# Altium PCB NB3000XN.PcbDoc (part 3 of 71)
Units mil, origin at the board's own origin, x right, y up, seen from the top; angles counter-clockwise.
Board outline 9527.56 x 6929.77 mil, 6 copper layers (Top Layer, GND+SHIELD, MidLayer1, MidLayer2, P2 - 3V3+5V0, Bottom Layer), stack 62.375 mil thick; 832 components, 1027 nets, 4655 pads, 4981 vias.
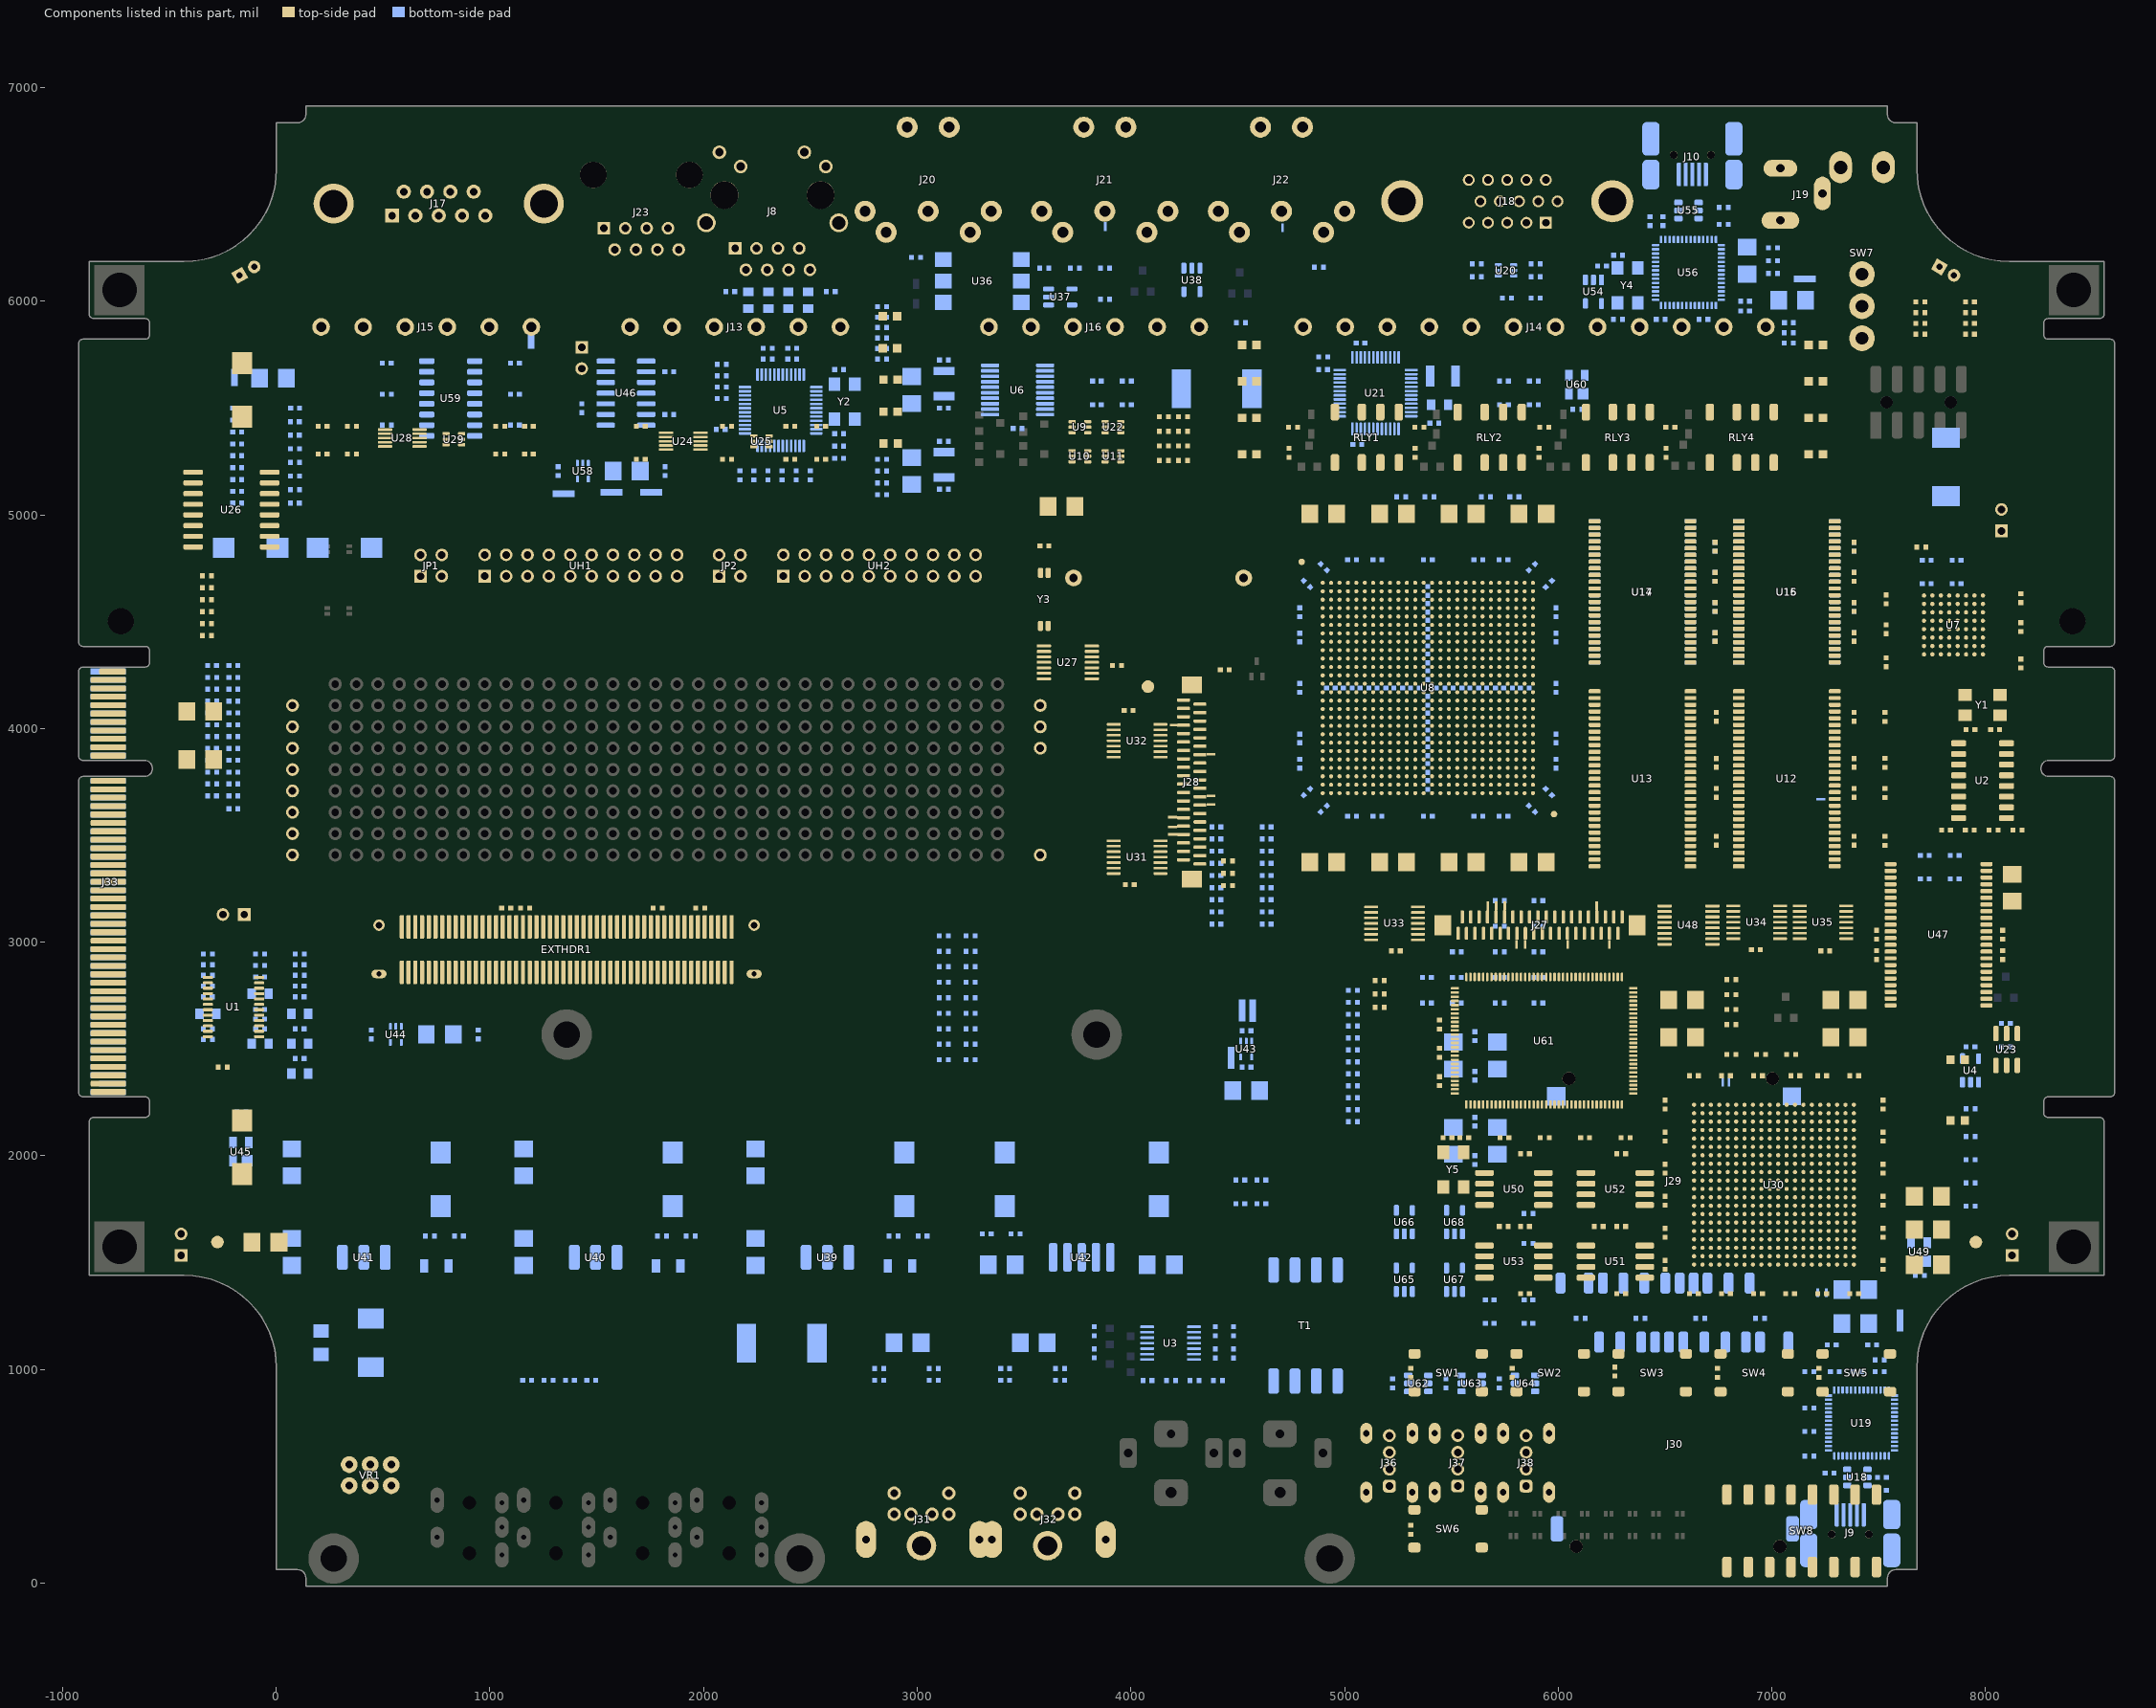
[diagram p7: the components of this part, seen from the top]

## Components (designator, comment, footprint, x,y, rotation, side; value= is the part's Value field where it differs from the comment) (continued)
R228 "100R 1%" RESC1005-STAR 3125,2812.5 r180 bottom locked (schematic designator R13)
R229 "100R 1%" RESC1005-STAR 3125,2667.5 r180 bottom locked (schematic designator R14)
R230 "100R 1%" RESC1005-STAR 3125,2522.5 r180 bottom locked (schematic designator R15)
R231 "100R 1%" RESC1005-STAR 3125,2595 r180 bottom locked (schematic designator R16)
R232 "4K7 1%" RESC1005-STAR 3250,2450 r0 bottom locked (schematic designator R17)
R233 "100R 1%" RESC1005-STAR 3125,2450 r180 bottom locked (schematic designator R18)
R234 "2K2 1%" RESC1005-STAR 1165,3160 r180 top (schematic designator R1)
R235 "2K2 1%" RESC1005-STAR 7530,3474.85 r270 top locked (schematic designator R275)
R236 "4K7 1%" RESC1005-STAR 5040,2719.09 r180 bottom locked (schematic designator R8)
R237 "4K7 1%" RESC1005-STAR 5040,2663.18 r180 bottom locked (schematic designator R7)
R238 "4K7 1%" RESC1005-STAR 5040,2607.27 r180 bottom locked (schematic designator R6)
R239 "4K7 1%" RESC1005-STAR 5040,2551.36 r180 bottom locked (schematic designator R5)
R240 "4K7 1%" RESC1005-STAR 5040,2495.45 r180 bottom locked (schematic designator R4)
R241 "4K7 1%" RESC1005-STAR 5040,2439.55 r180 bottom locked (schematic designator R3)
R242 "4K7 1%" RESC1005-STAR 5040,2383.64 r180 bottom locked (schematic designator R2)
R243 "4K7 1%" RESC1005-STAR 5040,2327.73 r180 bottom locked (schematic designator R1)
R244 "27R 1%" RESC1005-STAR 6280,5915 r180 bottom locked (schematic designator R1)
R245 "2K7 1%" RESC1005-STAR 7080,5805 r180 bottom locked (schematic designator R2)
R246 "5K6 1%" RESC1005-STAR 7080,5852.5 r180 bottom locked (schematic designator R3)
R247 "10K 1%" RESC1005-STAR 6775,6440 r180 bottom locked (schematic designator R4)
R248 "4K7 1%" RESC1005-STAR 7692.5,1440 r180 bottom locked (schematic designator R1000)
R249 "27R 1%" RESC1005-STAR 6775,6360 r180 bottom locked (schematic designator R6)
R250 "4K7 1%" RESC1005-STAR 7005,6250 r180 bottom locked (schematic designator R9)
R251 "4K7 1%" RESC1005-STAR 7005,6130 r180 bottom locked (schematic designator R8)
R252 "4K7 1%" RESC1005-STAR 7005,6190 r0 bottom locked (schematic designator R7)
R253 "4K7 1%" RESC1005-STAR 6665,1240 r180 bottom locked (schematic designator R1)
R254 "4K7 1%" RESC1005-STAR 6105,1240 r180 bottom locked (schematic designator R2)
R255 "4K7 1%" RESC1005-STAR 6385,1240 r0 bottom locked (schematic designator R1)
R256 "4K7 1%" RESC1005-STAR 6945,1240 r0 bottom locked (schematic designator R2)
R257 "12K 1%" RESC1005-STAR 5937.51,2085 r0 top locked (schematic designator R1)
R258 "12K 1%" RESC1005-STAR 6126.25,2085 r0 top locked (schematic designator R2)
R259 "12K 1%" RESC1005-STAR 6315,2085 r0 top locked (schematic designator R3)
R260 "10K 1%" RESC1005-STAR 5040,2775 r180 bottom locked (schematic designator R4)
R261 "150R 1%" RESC1005-STAR 5040,2271.82 r180 bottom locked (schematic designator R5)
R262 "150R 1%" RESC1005-STAR 5040,2215.91 r180 bottom locked (schematic designator R6)
R263 "150R 1%" RESC1005-STAR 5040,2160 r180 bottom locked (schematic designator R7)
R264 "2K2 1%" RESC1005-STAR 6810,2475 r0 top locked (schematic designator R269)
R265 "2K2 1%" RESC1005-STAR 6950,2475 r0 top locked (schematic designator R270)
R266 "2K2 1%" RESC1005-STAR 7090,2475 r0 top locked (schematic designator R271)
R267 "100R 1%" RESC1005-STAR 7926.99,5997 r0 top (schematic designator R154)
R268 "100R 1%" RESC1005-STAR 7695,5997 r0 top (schematic designator R155)
R269 "100R 1%" RESC1005-STAR 7926.99,5846 r0 top (schematic designator R156)
R270 "100R 1%" RESC1005-STAR 7695,5846 r0 top (schematic designator R157)
R271 "4K7 1%" RESC1005-STAR 6090,5495 r180 bottom locked (schematic designator R1000)
R272 "10K 1%" RESC1005-STAR 5445,2482.51 r90 top locked (schematic designator R268)
R273 "10K 1%" RESC1005-STAR 5445,2615 r90 top locked (schematic designator R264)
R274 "10K 1%" RESC1005-STAR 5225,935 r270 bottom locked (schematic designator R265)
R275 "10K 1%" RESC1005-STAR 5475,935 r90 bottom locked (schematic designator R266)
R276 "10K 1%" RESC1005-STAR 5725,935 r270 bottom locked (schematic designator R267)
R277 "4K7 1%" RESC1005-STAR 1785.16,3160.02 r180 top
R278 "4K7 1%" RESC1005-STAR 1985.52,3160.03 r180 top
R279 "4K7 1%" RESC1005-STAR 7926.99,5946.67 r0 top
R280 "4K7 1%" RESC1005-STAR 7695,5946.67 r0 top
R281 "4K7 1%" RESC1005-STAR 7926.99,5896.33 r0 top
R282 "4K7 1%" RESC1005-STAR 7695,5896.33 r0 top
R283 "4K7 1%" RESC1005-STAR 1076.56,3160 r180 top
RLY1 "IMO3 - 5VDC" IM03GR 4955,5245 r270 top locked
RLY2 "IMO3 - 5VDC" IM03GR 5530,5245 r270 top locked (schematic designator RLY1)
RLY3 "IMO3 - 5VDC" IM03GR 6130,5245 r270 top locked (schematic designator RLY1)
RLY4 "IMO3 - 5VDC" IM03GR 6710,5245 r270 top locked (schematic designator RLY1)
SW1 "SPNO" SW_DTSM-61NT/R 5485,985.39 r0 top locked
SW2 "SPNO" SW_DTSM-61NT/R 5962.5,985.39 r0 top locked
SW3 "SPNO" SW_DTSM-61NT/R 6440,985.39 r0 top locked
SW4 "SPNO" SW_DTSM-61NT/R 6917.5,985 r0 top locked
SW5 "SPNO" SW_DTSM-61NT/R 7395,985 r0 top locked
SW6 "SPNO" SW_DTSM-61NT/R 5485,255 r180 top locked (schematic designator SW1)
SW7 "SPDT SUB" T8019L-TNQ 7422,6920 r0 bottom locked (schematic designator SW1)
SW8 "219-8LPST" 219-8LPST 7140,245 r90 top locked (schematic designator SW1)
T1 "PT4812" PT4812 4668,1466 r0 bottom locked
TP1 "GND" TESTPIN 76.12,4108.23 r180 top locked
TP2 "5V0" TESTPIN 76.12,4008.23 r180 top locked
TP3 "+B" TESTPIN 3576.12,3908.23 r0 top locked
TP4 "3V3" TESTPIN 76.12,3908.23 r180 top locked
TP5 "2V5" TESTPIN 76.12,3808.23 r180 top locked
TP6 "1V8" TESTPIN 76.12,3708.23 r180 top locked
TP7 "1V2" TESTPIN 76.12,3608.23 r180 top locked
TP8 "GND" TESTPIN 3576.12,4008.23 r0 top locked
TP9 "MIXER LEFT" TESTPIN 76.12,3508.23 r180 top locked (schematic designator TP1)
TP10 "MIXER RIGHT" TESTPIN 76.12,3408.23 r180 top locked (schematic designator TP2)
TP11 "32K768HZ" TESTPIN 3576.12,4108.23 r0 top locked (schematic designator TP1)
TP12 "VBATT" TESTPIN 3576.12,3408.23 r0 top locked (schematic designator TP15)
U1 "CS4270" TSSOP-24 -320,2835 r270 top locked
U2 "ICS307-02" SOIC127P600-16 7986.38,3756.34 r270 top locked (schematic designator U1)
U3 "74HCU04" TSSOP14 4295,1200 r180 bottom locked (schematic designator U1)
U4 "SN74LVC1G04DBV" SOT95P280-5 7930,2400 r180 bottom locked (schematic designator U1)
U5 "RTL8201CL" TSQFP50P900X900-48 2360.87,5490 r90 bottom locked (schematic designator U1)
U6 "SN74LVC244ADB" SOP65P780-20 3470,5585 r270 bottom locked (schematic designator U2)
U7 "S29GL128P11FFI010" BGA100P8X8-64 7850,4485 r180 top locked (schematic designator U1)
U8 "XC3S1400AN-4FG676C" BGA100P26X26-676 5390,4190 r0 top locked (schematic designator U1)
U9 "SMF05C" SC70_6L 3725,5436.18 r270 top locked (schematic designator U2)
U10 "SMF05C" SC70_6L 3725,5300 r270 top locked (schematic designator U2)
U11 "SMF05C" SC70_6L 3880,5300 r270 top locked (schematic designator U2)
U12 "SDRAM-16Mx16" TSOP80P1176-54 7070,3765 r270 top locked (schematic designator U1)
U13 "SDRAM-16Mx16" TSOP80P1176-54 6395,3765 r270 top locked (schematic designator U2)
U14 "SRAM-256Kx16" TSOP80P1176-44 6395,4640 r270 bottom locked (schematic designator U1_SM)
U15 "SRAM-256Kx16" TSOP80P1176-44 7070,4640 r270 bottom locked (schematic designator U1_SM)
U16 "SRAM-256Kx16" TSOP80P1176-44 7070,4640 r270 top locked (schematic designator U1)
U17 "SRAM-256Kx16" TSOP80P1176-44 6395,4640 r270 top locked (schematic designator U2)
U18 "NUP2201MR6T1G" TSOP95P275-6 7400,495 r90 bottom locked (schematic designator U2)
U19 "CY7C68001-56LFC" QFN50P800X800_HS-57 7420,750 r180 bottom locked (schematic designator U3)
U20 "SMF05C" SC70_6L 5792.17,6170 r270 bottom locked (schematic designator U1)
U21 "THS8134BCPHP" TSQFP50P900X900_HS-48 5145,5570 r180 bottom locked (schematic designator U1)
U22 "SMF05C" SC70_6L 3880,5436.18 r270 top locked (schematic designator U2)
U23 "DS2502P" DSO-C6-D4 8099,2498.01 r180 top locked (schematic designator U1)
U24 "ADC084S021" TSSOP50P490-10AN 1905,5345 r180 top locked (schematic designator U1)
U25 "SMF05C" SC70_6L 2235,5370 r270 top locked (schematic designator U2)
U26 "PT2300-S" SOIC127P1030-16N -210,5025 r0 top locked (schematic designator U1)
U27 "PCF2123TS" TSOP65P640-14AN 3705,4310 r0 top locked (schematic designator U5)
U28 "DAC084S085CIMM" TSSOP50P490-10AN 590,5360 r0 top locked (schematic designator U1)
U29 "SMF05C" SC70_6L 795,5380 r270 top locked (schematic designator U2)
U30 "XC3S400AN-4FGG400C" FGG400 7010,1865 r270 top locked (schematic designator U1)
U31 "74VHC04" TSSOP14 3920,3475 r0 top locked (schematic designator U1)
U32 "74VHC04" TSSOP14 3920,4020 r0 top locked (schematic designator U1)
U33 "74VHC04" TSSOP14 5125,3165 r0 top locked (schematic designator U1)
U34 "74VHC04" TSSOP14 6820,3170 r0 top locked (schematic designator U1)
U35 "74VHC04" TSSOP14 7130,3170 r0 top locked (schematic designator U1)
U36 "4N35S" H11L1SR2VM 3305,6095 r90 bottom locked (schematic designator U1)
U37 "SN74LVC1G04DBV" SOT95P280-5 3670,6020 r90 bottom locked (schematic designator U2)
U38 "SN74LVC1G04DBV" SOT95P280-5 4285.84,6100 r0 bottom locked (schematic designator U3)
U39 "AP1084KL" TO254P-3N 2580,1775 r90 bottom locked (schematic designator U1)
U40 "AP1084KL" TO254P-3N 1495,1775 r90 bottom locked (schematic designator U1)
U41 "AP1084KL" TO254P-3N 410,1775 r90 bottom locked (schematic designator U1)
U42 "NCP630A" TO-263-2 3770,1525 r180 bottom locked (schematic designator U1)
U43 "TC1017R-3.3VLTTR" SOT65P210X80-5N 4540,2500 r270 bottom locked (schematic designator U1)
U44 "TC1017R-3.3VLTTR" SOT65P210X80-5N 560,2568.37 r270 bottom locked (schematic designator U1)
U45 "MAX6315US26D1" SOT143 -165.45,2020 r180 bottom locked (schematic designator U2000)
U46 "ISL8491IB" SOIC127P600-14N 1637.05,5570.08 r180 bottom locked (schematic designator U1)
U47 "SRAM-256Kx16" TSOP80P1176-44 7780,3035 r270 top locked (schematic designator U1_SM)
U48 "XPT2046" TSOP65P640-16AN 6610,3080 r0 top locked (schematic designator U1)
U49 "MAX6315US26D1" SOT143 7689.55,1550 r180 bottom locked (schematic designator U1000)
U50 "M25P80-VMW6 8Mbit Serial Flash" SOIC8-200-BODY 5655,1920 r270 top locked (schematic designator U1)
U51 "M25P80-VMW6 8Mbit Serial Flash" SOIC8-200-BODY 6130,1580 r270 top locked (schematic designator U1)
U52 "M25P80-VMW6 8Mbit Serial Flash" SOIC8-200-BODY 6130,1920 r270 top locked (schematic designator U1)
U53 "M25P80-VMW6 8Mbit Serial Flash" SOIC8-200-BODY 5655,1580 r270 top locked (schematic designator U2)
U54 "SN74LVC1G04DBV" SOT95P280-5 6165,6045 r0 bottom locked (schematic designator U1)
U55 "NUP2201MR6T1G" TSOP95P275-6 6610,6425 r270 bottom locked (schematic designator U2)
U56 "CY7C68001-56LFC" QFN50P800X800_HS-57 6610,6135 r0 bottom locked (schematic designator U3)
U58 "TC1017R-3.3VLTTR" SOT65P210X80-5N 1435,5205 r270 bottom locked (schematic designator U1)
U59 "HIN232ACBNZ-T" SOIC127P600-16 816.8,5545.08 r270 bottom locked (schematic designator U45)
U60 "MAX6315US26D1" SOT143 6087.05,5610 r180 bottom locked (schematic designator U1000)
U61 "ISP1760" SOT425-1 5570,2240 r0 top locked (schematic designator U59)
U62 "NUP2201MR6T1G" TSOP95P275-6 5345,935 r270 bottom locked (schematic designator U60)
U63 "NUP2201MR6T1G" TSOP95P275-6 5595,935 r270 bottom locked (schematic designator U61)
U64 "NUP2201MR6T1G" TSOP95P275-6 5845,935 r270 bottom locked (schematic designator U62)
U65 "SN74LVC1G04DBV" SOT95P280-5 5280,1420 r180 bottom locked
U66 "SN74LVC1G04DBV" SOT95P280-5 5280,1690 r180 bottom locked
U67 "SN74LVC1G04DBV" SOT95P280-5 5515,1420 r180 bottom locked (schematic designator U65)
U68 "SN74LVC1G04DBV" SOT95P280-5 5515,1690 r180 bottom locked (schematic designator U66)
UH1 "2x10 HEADER" HDR2X10 976.12,4713.23 r0 top locked
UH2 "2x10 HEADER" HDR2X10 2373.76,4713.23 r0 top locked
VR1 "2x5K linear" POT-R0911G-A1 440,555 r180 bottom locked
Y1 "20MHZ" XTAL-200X126-4 7986.38,4110 r0 top locked
Y2 "25MHz" XTAL-200X126-4 2660,5530 r270 bottom locked (schematic designator Y1)
Y3 "32.768 kHz 7pF" ECS-71 3595,4605 r90 top locked (schematic designator Y1)
Y4 "24MHz" XTAL-200X126-4 6325,6075 r270 bottom locked (schematic designator Y1)
Y5 "12MHz XTAL" XTAL-200X126-4 5510,1935 r270 top locked (schematic designator Y1)

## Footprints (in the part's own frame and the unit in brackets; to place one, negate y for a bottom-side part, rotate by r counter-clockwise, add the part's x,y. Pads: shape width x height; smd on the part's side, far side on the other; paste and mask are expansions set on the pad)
219-8LPST [mm] "Surface Mount DIP Switch, 8-way, Gull Wing Leads"
  rrect50% 2.44x1.13 smd: 1(-4.3,8.89) 2(-4.3,6.35) 3(-4.3,3.81) 4(-4.3,1.27) 5(-4.3,-1.27) 6(-4.3,-3.81) 7(-4.3,-6.35) 8(-4.3,-8.89) 9(4.3,-8.89) 10(4.3,-6.35) 11(4.3,-3.81) 12(4.3,-1.27) 13(4.3,1.27) 14(4.3,3.81) 15(4.3,6.35) 16(4.3,8.89)
  silkscreen extent -4.42,-11.04 2.68,11.04, body extent -5.1,-11.4 5.08,11.4, height 3.37
0603LED_GREEN [mm]
  rect 1x1 smd paste+0 mask+0: 1(0.85,0) 2(-0.85,0)
  silkscreen extent -1.97,-0.85 1.6,0.85, body extent -0.92,-0.53 1.09,0.53, height 0.46
0603LED_ORANGE [mm]
  rect 1x1 smd paste+0 mask+0: 1(0.85,0) 2(-0.85,0)
  silkscreen extent -1.97,-0.85 1.6,0.85, body extent -0.92,-0.53 1.09,0.53, height 0.46
0603LED_RED [mm]
  rect 1x1 smd paste+0 mask+0: 1(0.85,0) 2(-0.85,0)
  silkscreen extent -1.97,-0.85 1.6,0.85, body extent -0.92,-0.53 1.09,0.53, height 0.46
0603LED_YELLOW [mm]
  rect 1x1 smd paste+0 mask+0: 1(0.85,0) 2(-0.85,0)
  silkscreen extent -1.97,-0.85 1.6,0.85, body extent -0.92,-0.53 1.09,0.53, height 0.46
53751 [mm]
  rrect50% 0.508x2.8 smd: 1(-19.6,-2.7) 2(-19.6,2.7) 3(-18.8,-2.7) 4(-18.8,2.7) 5(-18,-2.7) 6(-18,2.7) 7(-17.2,-2.7) 8(-17.2,2.7) 9(-16.4,-2.7) 10(-16.4,2.7) 11(-15.6,-2.7) 12(-15.6,2.7) 13(-14.8,-2.7) 14(-14.8,2.7) 15(-14,-2.7) 16(-14,2.7) 17(-13.2,-2.7) 18(-13.2,2.7) 19(-12.4,-2.7) 20(-12.4,2.7) 21(-11.6,-2.7) 22(-11.6,2.7) 23(-10.8,-2.7) 24(-10.8,2.7) 25(-10,-2.7) 26(-10,2.7) 27(-9.2,-2.7) 28(-9.2,2.7) 29(-8.4,-2.7) 30(-8.4,2.7) 31(-7.6,-2.7) 32(-7.6,2.7) 33(-6.8,-2.7) 34(-6.8,2.7) 35(-6,-2.7) 36(-6,2.7) 37(-5.2,-2.7) 38(-5.2,2.7) 39(-4.4,-2.7) 40(-4.4,2.7) 41(-3.6,-2.7) 42(-3.6,2.7) 43(-2.8,-2.7) 44(-2.8,2.7) 45(-2,-2.7) 46(-2,2.7) 47(-1.2,-2.7) 48(-1.2,2.7) 49(-0.4,-2.7) 50(-0.4,2.7) 51(0.4,-2.7) 52(0.4,2.7) 53(1.2,-2.7) 54(1.2,2.7) 55(2,-2.7) 56(2,2.7) 57(2.8,-2.7) 58(2.8,2.7) 59(3.6,-2.7) 60(3.6,2.7) 61(4.4,-2.7) 62(4.4,2.7) 63(5.2,-2.7) 64(5.2,2.7) 65(6,-2.7) 66(6,2.7) 67(6.8,-2.7) 68(6.8,2.7) 69(7.6,-2.7) 70(7.6,2.7) 71(8.4,-2.7) 72(8.4,2.7) 73(9.2,-2.7) 74(9.2,2.7) 75(10,-2.7) 76(10,2.7) 77(10.8,-2.7) 78(10.8,2.7) 79(11.6,-2.7) 80(11.6,2.7) 81(12.4,-2.7) 82(12.4,2.7) 83(13.2,-2.7) 84(13.2,2.7) 85(14,-2.7) 86(14,2.7) 87(14.8,-2.7) 88(14.8,2.7) 89(15.6,-2.7) 90(15.6,2.7) 91(16.4,-2.7) 92(16.4,2.7) 93(17.2,-2.7) 94(17.2,2.7) 95(18,-2.7) 96(18,2.7) 97(18.8,-2.7) 98(18.8,2.7) 99(19.6,-2.7) 100(19.6,2.7)
  round 1.35 hole 0.8: MH1(-22.283,-2.9) MH3(22.317,-2.9)
  oval 1.8x1 hole 0.6 slot 1.4 at 0 deg: MH2(-22.283,2.9) MH4(22.317,2.9)
  silkscreen extent -30,-4.77 30.05,4.5, body extent -30.33,-4.4 30.37,4.4, height 11.7
482040001 [mm] "USB A Type Up-Right Reverse Connector, Pb-Free version"
  rrect50% 1.52x1.52 hole 0.9: 1(0,7.73)
  round 1.52 hole 0.9: 2(0,9.73) 3(0,11.73) 4(0,13.73)
  oval 1.4x2.5 hole 0.75 slot 1.5 at 90 deg: MH1(-2.735,7) MH2(2.735,7) MH3(-2.735,14) MH4(2.735,14)
  silkscreen extent -3.6,-4.64 3.6,15.75, body extent -3.61,-4.71 3.59,14.54, height 14.68
955012881 [mm] "Connector; PCB Jack, Thru-Hole; 1-Port, 8 Positions, 8 Loaded; Shielded without Lightpipes; Vertical"
  rect 1.5x1.5 hole 0.9: 1(-4.445,3.43)
  round 1.5 hole 0.9: 2(-3.175,5.97) 3(-1.905,3.43) 4(-0.635,5.97) 5(0.635,3.43) 6(1.905,5.97) 7(3.175,3.43) 8(4.445,5.97)
  round 3.15 hole 3.15 unplated: MH1(-5.715,-2.92) MH2(5.715,-2.92)
  silkscreen extent -7.62,-10.8 7.62,7.3, body extent -7.53,-145.72 7.51,7.04, height 23.16
BGA100P8X8-64 [mil] "AMD 64-Ball Fortfied Ball grid Array (FBGA)"
  round 20 smd: A1(-137.8,-137.8) A2(-137.8,-98.43) A3(-137.8,-59.06) A4(-137.8,-19.68) A5(-137.8,19.68) A6(-137.8,59.06) A7(-137.8,98.43) A8(-137.8,137.8) B1(-98.43,-137.8) B2(-98.43,-98.43) B3(-98.43,-59.06) B4(-98.43,-19.69) B5(-98.43,19.68) B6(-98.43,59.06) B7(-98.43,98.43) B8(-98.43,137.8) C1(-59.06,-137.8) C2(-59.06,-98.43) C3(-59.06,-59.06) C4(-59.06,-19.69) C5(-59.06,19.68) C6(-59.06,59.06) C7(-59.06,98.43) C8(-59.06,137.8) D1(-19.69,-137.8) D2(-19.69,-98.43) D3(-19.69,-59.06) D4(-19.69,-19.69) D5(-19.69,19.68) D6(-19.69,59.06) D7(-19.69,98.43) D8(-19.69,137.8) E1(19.68,-137.8) E2(19.68,-98.43) E3(19.68,-59.06) E4(19.68,-19.69) E5(19.68,19.68) E6(19.68,59.06) E7(19.68,98.43) E8(19.68,137.8) F1(59.05,-137.8) F2(59.05,-98.43) F3(59.05,-59.06) F4(59.05,-19.69) F5(59.05,19.68) F6(59.05,59.06) F7(59.05,98.43) F8(59.05,137.8) G1(98.42,-137.8) G2(98.42,-98.43) G3(98.42,-59.06) G4(98.42,-19.69) G5(98.42,19.68) G6(98.42,59.06) G7(98.43,98.43) G8(98.42,137.8) H1(137.8,-137.8) H2(137.8,-98.43) H3(137.8,-59.06) H4(137.8,-19.69) H5(137.8,19.68) H6(137.8,59.06) H7(137.8,98.43) H8(137.8,137.8)
  silkscreen extent -256,-250 256,217, body extent -250,-213 252,211, height 39
BGA100P26X26-676 [mm]
  round 0.483 smd: A1(-12.5,12.5) A2(-11.5,12.5) A3(-10.5,12.5) A4(-9.5,12.5) A5(-8.5,12.5) A6(-7.5,12.5) A7(-6.5,12.5) A8(-5.5,12.5) A9(-4.5,12.5) A10(-3.5,12.5) A11(-2.5,12.5) A12(-1.5,12.5) A13(-0.5,12.5) A14(0.5,12.5) A15(1.5,12.5) A16(2.5,12.5) A17(3.5,12.5) A18(4.5,12.5) A19(5.5,12.5) A20(6.5,12.5) A21(7.5,12.5) A22(8.5,12.5) A23(9.5,12.5) A24(10.5,12.5) A25(11.5,12.5) A26(12.5,12.5) AA1(-12.5,-7.5) AA2(-11.5,-7.5) AA3(-10.5,-7.5) AA4(-9.5,-7.5) AA5(-8.5,-7.5) AA6(-7.5,-7.5) AA7(-6.5,-7.5) AA8(-5.5,-7.5) AA9(-4.5,-7.5) AA10(-3.5,-7.5) AA11(-2.5,-7.5) AA12(-1.5,-7.5) AA13(-0.5,-7.5) AA14(0.5,-7.5) AA15(1.5,-7.5) AA16(2.5,-7.5) AA17(3.5,-7.5) AA18(4.5,-7.5) AA19(5.5,-7.5) AA20(6.5,-7.5) AA21(7.5,-7.5) AA22(8.5,-7.5) AA23(9.5,-7.5) AA24(10.5,-7.5) AA25(11.5,-7.5) AA26(12.5,-7.5) AB1(-12.5,-8.5) AB2(-11.5,-8.5) AB3(-10.5,-8.5) AB4(-9.5,-8.5) AB5(-8.5,-8.5) AB6(-7.5,-8.5) AB7(-6.5,-8.5) AB8(-5.5,-8.5) AB9(-4.5,-8.5) AB10(-3.5,-8.5) AB11(-2.5,-8.5) AB12(-1.5,-8.5) AB13(-0.5,-8.5) AB14(0.5,-8.5) AB15(1.5,-8.5) AB16(2.5,-8.5) AB17(3.5,-8.5) AB18(4.5,-8.5) AB19(5.5,-8.5) AB20(6.5,-8.5) AB21(7.5,-8.5) AB22(8.5,-8.5) AB23(9.5,-8.5) AB24(10.5,-8.5) AB25(11.5,-8.5) AB26(12.5,-8.5) AC1(-12.5,-9.5) AC2(-11.5,-9.5) AC3(-10.5,-9.5) AC4(-9.5,-9.5) AC5(-8.5,-9.5) AC6(-7.5,-9.5) AC7(-6.5,-9.5) AC8(-5.5,-9.5) AC9(-4.5,-9.5) AC10(-3.5,-9.5) AC11(-2.5,-9.5) AC12(-1.5,-9.5) AC13(-0.5,-9.5) AC14(0.5,-9.5) AC15(1.5,-9.5) AC16(2.5,-9.5) AC17(3.5,-9.5) AC18(4.5,-9.5) AC19(5.5,-9.5) AC20(6.5,-9.5) AC21(7.5,-9.5) AC22(8.5,-9.5) AC23(9.5,-9.5) AC24(10.5,-9.5) AC25(11.5,-9.5) AC26(12.5,-9.5) AD1(-12.5,-10.5) AD2(-11.5,-10.5) AD3(-10.5,-10.5) AD4(-9.5,-10.5) AD5(-8.5,-10.5) AD6(-7.5,-10.5) AD7(-6.5,-10.5) AD8(-5.5,-10.5) AD9(-4.5,-10.5) AD10(-3.5,-10.5) AD11(-2.5,-10.5) AD12(-1.5,-10.5) AD13(-0.5,-10.5) AD14(0.5,-10.5) AD15(1.5,-10.5) AD16(2.5,-10.5) AD17(3.5,-10.5) AD18(4.5,-10.5) AD19(5.5,-10.5) AD20(6.5,-10.5) AD21(7.5,-10.5) AD22(8.5,-10.5) AD23(9.5,-10.5) AD24(10.5,-10.5) AD25(11.5,-10.5) AD26(12.5,-10.5) AE1(-12.5,-11.5) AE2(-11.5,-11.5) AE3(-10.5,-11.5) AE4(-9.5,-11.5) AE5(-8.5,-11.5) AE6(-7.5,-11.5) AE7(-6.5,-11.5) AE8(-5.5,-11.5) AE9(-4.5,-11.5) AE10(-3.5,-11.5) AE11(-2.5,-11.5) AE12(-1.5,-11.5) AE13(-0.5,-11.5) AE14(0.5,-11.5) AE15(1.5,-11.5) AE16(2.5,-11.5) AE17(3.5,-11.5) AE18(4.5,-11.5) AE19(5.5,-11.5) AE20(6.5,-11.5) AE21(7.5,-11.5) AE22(8.5,-11.5) AE23(9.5,-11.5) AE24(10.5,-11.5) AE25(11.5,-11.5) AE26(12.5,-11.5) AF1(-12.5,-12.5) AF2(-11.5,-12.5) AF3(-10.5,-12.5) AF4(-9.5,-12.5) AF5(-8.5,-12.5) AF6(-7.5,-12.5) AF7(-6.5,-12.5) AF8(-5.5,-12.5) AF9(-4.5,-12.5) AF10(-3.5,-12.5) AF11(-2.5,-12.5) AF12(-1.5,-12.5) AF13(-0.5,-12.5) AF14(0.5,-12.5) AF15(1.5,-12.5) AF16(2.5,-12.5) AF17(3.5,-12.5) AF18(4.5,-12.5) AF19(5.5,-12.5) AF20(6.5,-12.5) AF21(7.5,-12.5) AF22(8.5,-12.5) AF23(9.5,-12.5) AF24(10.5,-12.5) AF25(11.5,-12.5) AF26(12.5,-12.5) B1(-12.5,11.5) B2(-11.5,11.5) B3(-10.5,11.5) B4(-9.5,11.5) B5(-8.5,11.5) B6(-7.5,11.5) B7(-6.5,11.5) B8(-5.5,11.5) B9(-4.5,11.5) B10(-3.5,11.5) B11(-2.5,11.5) B12(-1.5,11.5) B13(-0.5,11.5) B14(0.5,11.5) B15(1.5,11.5) B16(2.5,11.5) B17(3.5,11.5) B18(4.5,11.5) B19(5.5,11.5) B20(6.5,11.5) B21(7.5,11.5) B22(8.5,11.5) B23(9.5,11.5) B24(10.5,11.5) B25(11.5,11.5) B26(12.5,11.5) C1(-12.5,10.5) C2(-11.5,10.5) C3(-10.5,10.5) C4(-9.5,10.5) C5(-8.5,10.5) C6(-7.5,10.5) C7(-6.5,10.5) C8(-5.5,10.5) C9(-4.5,10.5) C10(-3.5,10.5) C11(-2.5,10.5) C12(-1.5,10.5) C13(-0.5,10.5) C14(0.5,10.5) C15(1.5,10.5) C16(2.5,10.5) C17(3.5,10.5) C18(4.5,10.5) C19(5.5,10.5) C20(6.5,10.5) C21(7.5,10.5) C22(8.5,10.5) C23(9.5,10.5) C24(10.5,10.5) C25(11.5,10.5) C26(12.5,10.5) D1(-12.5,9.5) D2(-11.5,9.5) D3(-10.5,9.5) D4(-9.5,9.5) D5(-8.5,9.5) D6(-7.5,9.5) D7(-6.5,9.5) D8(-5.5,9.5) D9(-4.5,9.5) D10(-3.5,9.5) D11(-2.5,9.5) D12(-1.5,9.5) D13(-0.5,9.5) D14(0.5,9.5) D15(1.5,9.5) D16(2.5,9.5) D17(3.5,9.5) D18(4.5,9.5) D19(5.5,9.5) D20(6.5,9.5) D21(7.5,9.5) D22(8.5,9.5) D23(9.5,9.5) D24(10.5,9.5) D25(11.5,9.5) D26(12.5,9.5) E1(-12.5,8.5) E2(-11.5,8.5) E3(-10.5,8.5) E4(-9.5,8.5) E5(-8.5,8.5) E6(-7.5,8.5) E7(-6.5,8.5) E8(-5.5,8.5) E9(-4.5,8.5) E10(-3.5,8.5) E11(-2.5,8.5) E12(-1.5,8.5) E13(-0.5,8.5) E14(0.5,8.5) E15(1.5,8.5) E16(2.5,8.5) E17(3.5,8.5) E18(4.5,8.5) E19(5.5,8.5) E20(6.5,8.5) E21(7.5,8.5) E22(8.5,8.5) E23(9.5,8.5) E24(10.5,8.5) E25(11.5,8.5) E26(12.5,8.5) F1(-12.5,7.5) F2(-11.5,7.5) F3(-10.5,7.5) F4(-9.5,7.5) F5(-8.5,7.5) F6(-7.5,7.5) F7(-6.5,7.5) F8(-5.5,7.5) F9(-4.5,7.5) F10(-3.5,7.5) F11(-2.5,7.5) F12(-1.5,7.5) F13(-0.5,7.5) F14(0.5,7.5) F15(1.5,7.5) F16(2.5,7.5) F17(3.5,7.5) F18(4.5,7.5) F19(5.5,7.5) F20(6.5,7.5) F21(7.5,7.5) F22(8.5,7.5) F23(9.5,7.5) F24(10.5,7.5) F25(11.5,7.5) F26(12.5,7.5) G1(-12.5,6.5) G2(-11.5,6.5) G3(-10.5,6.5) G4(-9.5,6.5) G5(-8.5,6.5) G6(-7.5,6.5) G7(-6.5,6.5) G8(-5.5,6.5) G9(-4.5,6.5) G10(-3.5,6.5) G11(-2.5,6.5) G12(-1.5,6.5) G13(-0.5,6.5) G14(0.5,6.5) G15(1.5,6.5) G16(2.5,6.5) G17(3.5,6.5) G18(4.5,6.5) G19(5.5,6.5) G20(6.5,6.5) G21(7.5,6.5) G22(8.5,6.5) G23(9.5,6.5) G24(10.5,6.5) G25(11.5,6.5) G26(12.5,6.5) H1(-12.5,5.5) H2(-11.5,5.5) H3(-10.5,5.5) H4(-9.5,5.5) H5(-8.5,5.5) H6(-7.5,5.5) H7(-6.5,5.5) H8(-5.5,5.5) H9(-4.5,5.5) H10(-3.5,5.5) H11(-2.5,5.5) H12(-1.5,5.5) H13(-0.5,5.5) H14(0.5,5.5) H15(1.5,5.5) H16(2.5,5.5) H17(3.5,5.5) H18(4.5,5.5) H19(5.5,5.5) H20(6.5,5.5) H21(7.5,5.5) H22(8.5,5.5) H23(9.5,5.5) H24(10.5,5.5) H25(11.5,5.5) H26(12.5,5.5) J1(-12.5,4.5) J2(-11.5,4.5) J3(-10.5,4.5) J4(-9.5,4.5) J5(-8.5,4.5) J6(-7.5,4.5) J7(-6.5,4.5) J8(-5.5,4.5) J9(-4.5,4.5) J10(-3.5,4.5) J11(-2.5,4.5) J12(-1.5,4.5) J13(-0.5,4.5) J14(0.5,4.5) J15(1.5,4.5) J16(2.5,4.5) J17(3.5,4.5) J18(4.5,4.5) J19(5.5,4.5) J20(6.5,4.5) J21(7.5,4.5) J22(8.5,4.5) J23(9.5,4.5) J24(10.5,4.5) J25(11.5,4.5) J26(12.5,4.5) K1(-12.5,3.5) K2(-11.5,3.5) K3(-10.5,3.5) K4(-9.5,3.5) K5(-8.5,3.5) K6(-7.5,3.5) K7(-6.5,3.5) K8(-5.5,3.5) K9(-4.5,3.5) K10(-3.5,3.5) K11(-2.5,3.5) K12(-1.5,3.5) K13(-0.5,3.5) K14(0.5,3.5) K15(1.5,3.5) K16(2.5,3.5) K17(3.5,3.5) K18(4.5,3.5) K19(5.5,3.5) K20(6.5,3.5) K21(7.5,3.5) K22(8.5,3.5) K23(9.5,3.5) K24(10.5,3.5) K25(11.5,3.5) K26(12.5,3.5) L1(-12.5,2.5) L2(-11.5,2.5) L3(-10.5,2.5) L4(-9.5,2.5) L5(-8.5,2.5) L6(-7.5,2.5) L7(-6.5,2.5) L8(-5.5,2.5) L9(-4.5,2.5) L10(-3.5,2.5) L11(-2.5,2.5) L12(-1.5,2.5) L13(-0.5,2.5) L14(0.5,2.5) L15(1.5,2.5) L16(2.5,2.5) L17(3.5,2.5) L18(4.5,2.5) L19(5.5,2.5) L20(6.5,2.5) L21(7.5,2.5) L22(8.5,2.5) L23(9.5,2.5) L24(10.5,2.5) L25(11.5,2.5) L26(12.5,2.5) M1(-12.5,1.5) M2(-11.5,1.5) M3(-10.5,1.5) M4(-9.5,1.5) M5(-8.5,1.5) M6(-7.5,1.5) M7(-6.5,1.5) M8(-5.5,1.5) M9(-4.5,1.5) M10(-3.5,1.5) M11(-2.5,1.5) M12(-1.5,1.5) M13(-0.5,1.5) M14(0.5,1.5) M15(1.5,1.5) M16(2.5,1.5) M17(3.5,1.5) M18(4.5,1.5) M19(5.5,1.5) M20(6.5,1.5) M21(7.5,1.5) M22(8.5,1.5) M23(9.5,1.5) M24(10.5,1.5) M25(11.5,1.5) M26(12.5,1.5) N1(-12.5,0.5) N2(-11.5,0.5) N3(-10.5,0.5) N4(-9.5,0.5) N5(-8.5,0.5) N6(-7.5,0.5) N7(-6.5,0.5) N8(-5.5,0.5) N9(-4.5,0.5) N10(-3.5,0.5) N11(-2.5,0.5) N12(-1.5,0.5) N13(-0.5,0.5) N14(0.5,0.5) N15(1.5,0.5) N16(2.5,0.5) N17(3.5,0.5) N18(4.5,0.5) N19(5.5,0.5) N20(6.5,0.5) N21(7.5,0.5) N22(8.5,0.5) N23(9.5,0.5) N24(10.5,0.5) N25(11.5,0.5) N26(12.5,0.5) P1(-12.5,-0.5) P2(-11.5,-0.5) P3(-10.5,-0.5) P4(-9.5,-0.5) P5(-8.5,-0.5) P6(-7.5,-0.5) P7(-6.5,-0.5) P8(-5.5,-0.5) P9(-4.5,-0.5) P10(-3.5,-0.5) P11(-2.5,-0.5) P12(-1.5,-0.5) P13(-0.5,-0.5) P14(0.5,-0.5) P15(1.5,-0.5) P16(2.5,-0.5) P17(3.5,-0.5) P18(4.5,-0.5) P19(5.5,-0.5) P20(6.5,-0.5) P21(7.5,-0.5) P22(8.5,-0.5) P23(9.5,-0.5) P24(10.5,-0.5) P25(11.5,-0.5) P26(12.5,-0.5) R1(-12.5,-1.5) R2(-11.5,-1.5) R3(-10.5,-1.5) R4(-9.5,-1.5) R5(-8.5,-1.5) R6(-7.5,-1.5) R7(-6.5,-1.5) R8(-5.5,-1.5) R9(-4.5,-1.5) R10(-3.5,-1.5) R11(-2.5,-1.5) R12(-1.5,-1.5) R13(-0.5,-1.5) R14(0.5,-1.5) R15(1.5,-1.5) R16(2.5,-1.5) R17(3.5,-1.5) R18(4.5,-1.5) R19(5.5,-1.5) R20(6.5,-1.5) R21(7.5,-1.5) R22(8.5,-1.5) R23(9.5,-1.5) R24(10.5,-1.5) R25(11.5,-1.5) R26(12.5,-1.5) T1(-12.5,-2.5) T2(-11.5,-2.5) T3(-10.5,-2.5) T4(-9.5,-2.5) T5(-8.5,-2.5) T6(-7.5,-2.5) T7(-6.5,-2.5) T8(-5.5,-2.5) T9(-4.5,-2.5) T10(-3.5,-2.5) T11(-2.5,-2.5) T12(-1.5,-2.5) T13(-0.5,-2.5) T14(0.5,-2.5) T15(1.5,-2.5) T16(2.5,-2.5) T17(3.5,-2.5) T18(4.5,-2.5) T19(5.5,-2.5) T20(6.5,-2.5) T21(7.5,-2.5) T22(8.5,-2.5) T23(9.5,-2.5) T24(10.5,-2.5) T25(11.5,-2.5) T26(12.5,-2.5) U1(-12.5,-3.5) U2(-11.5,-3.5) U3(-10.5,-3.5) U4(-9.5,-3.5) U5(-8.5,-3.5) U6(-7.5,-3.5) U7(-6.5,-3.5) U8(-5.5,-3.5) U9(-4.5,-3.5) U10(-3.5,-3.5) U11(-2.5,-3.5) U12(-1.5,-3.5) U13(-0.5,-3.5) U14(0.5,-3.5) U15(1.5,-3.5) U16(2.5,-3.5) U17(3.5,-3.5) U18(4.5,-3.5) U19(5.5,-3.5) U20(6.5,-3.5) U21(7.5,-3.5) U22(8.5,-3.5) U23(9.5,-3.5) U24(10.5,-3.5) U25(11.5,-3.5) U26(12.5,-3.5) V1(-12.5,-4.5) V2(-11.5,-4.5) V3(-10.5,-4.5) V4(-9.5,-4.5) V5(-8.5,-4.5) V6(-7.5,-4.5) V7(-6.5,-4.5) V8(-5.5,-4.5) V9(-4.5,-4.5) V10(-3.5,-4.5) V11(-2.5,-4.5) V12(-1.5,-4.5) V13(-0.5,-4.5) V14(0.5,-4.5) V15(1.5,-4.5) V16(2.5,-4.5) V17(3.5,-4.5) V18(4.5,-4.5) V19(5.5,-4.5) V20(6.5,-4.5) V21(7.5,-4.5) V22(8.5,-4.5) V23(9.5,-4.5) V24(10.5,-4.5) V25(11.5,-4.5) V26(12.5,-4.5) W1(-12.5,-5.5) W2(-11.5,-5.5) W3(-10.5,-5.5) W4(-9.5,-5.5) W5(-8.5,-5.5) W6(-7.5,-5.5) W7(-6.5,-5.5) W8(-5.5,-5.5) W9(-4.5,-5.5) W10(-3.5,-5.5) W11(-2.5,-5.5) W12(-1.5,-5.5) W13(-0.5,-5.5) W14(0.5,-5.5) W15(1.5,-5.5) W16(2.5,-5.5) W17(3.5,-5.5) W18(4.5,-5.5) W19(5.5,-5.5) W20(6.5,-5.5) W21(7.5,-5.5) W22(8.5,-5.5) W23(9.5,-5.5) W24(10.5,-5.5) W25(11.5,-5.5) W26(12.5,-5.5) Y1(-12.5,-6.5) Y2(-11.5,-6.5) Y3(-10.5,-6.5) Y4(-9.5,-6.5) Y5(-8.5,-6.5) Y6(-7.5,-6.5) Y7(-6.5,-6.5) Y8(-5.5,-6.5) Y9(-4.5,-6.5) Y10(-3.5,-6.5) Y11(-2.5,-6.5) Y12(-1.5,-6.5) Y13(-0.5,-6.5) Y14(0.5,-6.5) Y15(1.5,-6.5) Y16(2.5,-6.5) Y17(3.5,-6.5) Y18(4.5,-6.5) Y19(5.5,-6.5) Y20(6.5,-6.5) Y21(7.5,-6.5) Y22(8.5,-6.5) Y23(9.5,-6.5) Y24(10.5,-6.5) Y25(11.5,-6.5) Y26(12.5,-6.5)
  round 0.762 smd paste-0.762 mask+0.711: FID1(-15,15) FID1(15,-15)
  round 1 on Mech7 paste-0.55 mask+1: FID1(-15,15) FID1(15,-15)
  Top Layer circle w0.2: c15,-15 r1
  Top Layer circle w0.2: c-15,15 r1
  silkscreen extent -14.77,-13.5 13.5,13.5, body extent -13.53,-13.5 13.47,13.5, height 2.59
CAPC1005-STAR#1 [mm] "Chip Capacitor 1005"
  rect 0.6x0.6 smd: 1(-0.525,0) 2(0.525,0)
  silkscreen extent -0.05,-0.38 0.05,0.38, body extent -0.57,-0.3 0.57,0.3, height 0.4
CAPC1005-STAR#2 [mm] "Chip Capacitor 1005"
  rect 0.6x0.6 smd mask+0.038: 1(-0.525,0) 2(0.525,0)
  silkscreen extent -0.05,-0.38 0.05,0.38, body extent -0.57,-0.3 0.57,0.3, height 0.2
CAPC2012-STAR [mm] "0805 Capacitor SMD - Startronics"
  rect 1x1.25 smd: 1(-1,0) 2(1,0)
  silkscreen extent -0.4,-1 0.4,1, body extent -0.98,-0.64 0.87,0.6, height 0.8
CAPC3216-STAR [mm] "Capacitor 1206 (3216) for Startronics"
  rect 1x1.6 smd: 1(-1.45,0) 2(1.45,0)
  silkscreen extent -0.62,-1.1 0.62,1.1, body extent -1.64,-0.89 1.63,0.86, height 0.9
CAPC3528-STAR#1 [mm] "Capacitor 3.5x2.8mm (B-Case)"
  rect 2x2.2 smd: 1(-1.6,0) 2(1.6,0)
  silkscreen extent -3,-1.7 3.05,1.7, body extent -1.79,-1.54 1.8,1.54, height 1
CAPC3528-STAR#2 [mm] "Capacitor 3.5x2.8mm (B-Case)"
  rect 2x2.2 smd: 1(-1.6,0)
  rect 1.956x2.2 smd: 2(1.6,0)
  silkscreen extent -3,-1.7 3.05,1.7, body extent -1.79,-1.54 1.8,1.54, height 1
CAPC7343-STAR [mm] "Capcacitor SMD 7.3 x 4.3mm (D-Case)"
  rect 2.6x2.4 smd: 1(-3.202,0.007) 2(3.198,0.007)
  silkscreen extent -5.33,-2.39 5.08,2.41, body extent -3.49,-2.03 3.51,2.04, height 4.05
CAPM7163 [mm]
  rect 2.35x3.1 smd: 1(-2.875,0) 2(2.875,0)
  silkscreen extent -3.5,-3.15 3.5,3.15, body extent -3.1,-2.64 3.2,2.81, height 1.5
CELL_HOLDER [mm] "Lithium Battery Holder for CR2032 3V Cell"
  round 2 hole 1: 1(12.275,0) 2(-7.95,0)
  Top Layer region: -6.475,-3.6 -3.95,-3.6 -3.95,3.6 -6.475,3.6
  Top Layer region: -3.941,1.527 -3.941,3.602 -8.09,3.602 -8.09,1.527
  Top Layer region: -8.109,-1.527 -8.109,-3.602 -3.959,-3.602 -3.959,-1.527
  Top Layer region: 12.298,1.534 12.298,3.609 9.573,3.609 9.573,1.534
  Top Layer region: 9.577,-1.534 9.577,-3.609 12.302,-3.609 12.302,-1.534
  Top Layer region: 10.802,3.591 9.577,3.591 9.577,-3.609 10.802,-3.609
  silkscreen extent -10.6,-10.6 13.47,10.6, body extent -10.62,-10.59 13.17,10.63, height 10
CON_RJ45_RA_LEDS [mm]
  rect 1.5x1.5 hole 0.9: 1(-4.445,6.35)
  round 1.5 hole 0.9: 2(-3.175,8.89) 3(-1.905,6.35) 4(-0.635,8.89) 5(0.635,6.35) 6(1.905,8.89) 7(3.175,6.35) 8(4.445,8.89)
  round 1.62 hole 1: 9(-6.325,-5.08) 10(-3.785,-3.38) 11(3.785,-5.08) 12(6.325,-3.38)
  round 2.23 hole 1.6: MH1(-7.875,3.3) MH2(7.875,3.3)
  round 3.3 hole 3.3 unplated: MH3(-5.715,0) MH4(5.715,0)
  silkscreen extent -8,-10.7 8,10.6, body extent -7.9,-145.27 7.97,10.6, height 24.58
DB9_MALE [mm]
  rect 1.69x1.69 hole 0.9: 1(1.385,-2.84)
  round 1.69 hole 0.9: 2(-1.385,-2.84) 3(-4.155,-2.84) 4(-6.925,-2.84) 5(-9.695,-2.84) 6(0,0) 7(-2.77,0) 8(-5.54,0) 9(-8.31,0)
  round 4.76 hole 3.3: 10(-16.65,-1.42) 11(8.34,-1.42)
  silkscreen extent -19.56,-4.32 11.24,15.6, body extent -19.85,-4.33 11.47,16.38, height 12.66
DB15-VGA-FEMALE [mm]
  rect 1.4x1.4 hole 0.9: 1(0,0)
  round 1.4 hole 0.9: 2(2.29,0) 3(4.58,0) 4(6.87,0) 5(9.16,0) 6(-1.4,2.54) 7(0.89,2.54) 8(3.18,2.54) 9(5.47,2.54) 10(7.76,2.54) 11(0,5.08) 12(2.29,5.08) 13(4.58,5.08) 14(6.87,5.08) 15(9.16,5.08)
  round 5 hole 3.3: 16(-7.915,2.54) 17(17.075,2.54)
  silkscreen extent -10.83,-2.65 20.01,19.61, body extent -12.27,-1.67 21.42,60.12, height 14.3
DIOM8059 [mm] "DO-214-AB/SMC; 2 C-Bend Leads; Body 7.9 x 5.9 mm, inc. leads (LxW)"
  rect 2.4x3.3 smd: 1(-3.475,0) 2(3.475,0)
  silkscreen extent -5.07,-2.05 5.43,2.05, body extent -4.06,-2.92 4.19,2.92, height 1.42
DSO-C6-D4 [mm] "Small Outline; 6 C-Bend Leads; Body Width 3.8 mm; Pitch 1.27 mm"
  rrect50% 0.65x1.8 smd: 1(-1.27,-1.9) 2(0,-1.9) 3(1.27,-1.9) 4(1.27,1.9) 5(0,1.9) 6(-1.27,1.9)
  silkscreen extent -2.27,-2.02 2,1.95, body extent -1.86,-1.52 1.86,1.7, height 1.02
ECS-71 [mm] "SMD TUNING FORK CRYSTAL"
  rrect50% 1.2x0.6 smd: 1(-3.15,-0.45) 2(3.15,-0.45) 3(3.15,0.45) 4(-3.15,0.45)
  silkscreen extent -2.15,-0.75 2.15,0.75, body extent -3.59,-0.75 3.55,0.74, height 1.41
EDGE-PCIE-X8 [mm] "PCIe X8 PCB Edge Connector"
  rrect50% 0.7x3.2 smd paste-3.2: A1(0,-4)
  rrect50% 0.7x4.2 smd paste-4.2: A2(-1,-3.5) A3(-2,-3.5) A4(-3,-3.5) A5(-4,-3.5) A6(-5,-3.5) A7(-6,-3.5) A8(-7,-3.5) A9(-8,-3.5) A10(-9,-3.5) A11(-10,-3.5) A12(-13,-3.5) A13(-14,-3.5) A14(-15,-3.5) A15(-16,-3.5) A16(-17,-3.5) A17(-18,-3.5) A18(-19,-3.5) A19(-20,-3.5) A20(-21,-3.5) A21(-22,-3.5) A22(-23,-3.5) A23(-24,-3.5) A24(-25,-3.5) A25(-26,-3.5) A26(-27,-3.5) A27(-28,-3.5) A28(-29,-3.5) A29(-30,-3.5) A30(-31,-3.5) A31(-32,-3.5) A32(-33,-3.5) A33(-34,-3.5) A34(-35,-3.5) A35(-36,-3.5) A36(-37,-3.5) A37(-38,-3.5) A38(-39,-3.5) A39(-40,-3.5) A40(-41,-3.5) A41(-42,-3.5) A42(-43,-3.5) A43(-44,-3.5) A44(-45,-3.5) A45(-46,-3.5) A46(-47,-3.5) A47(-48,-3.5) A48(-49,-3.5) A49(-50,-3.5)
  rrect0% 0.7x4.2 smd far side paste-4.2: B1(0,-3.5) B2(-1,-3.5) B3(-2,-3.5) B4(-3,-3.5) B5(-4,-3.5) B6(-5,-3.5) B7(-6,-3.5) B8(-7,-3.5) B9(-8,-3.5) B10(-9,-3.5) B11(-10,-3.5) B12(-13,-3.5) B13(-14,-3.5) B14(-15,-3.5) B15(-16,-3.5) B16(-17,-3.5) B18(-19,-3.5) B19(-20,-3.5) B20(-21,-3.5) B21(-22,-3.5) B22(-23,-3.5) B23(-24,-3.5) B24(-25,-3.5) B25(-26,-3.5) B26(-27,-3.5) B27(-28,-3.5) B28(-29,-3.5) B29(-30,-3.5) B30(-31,-3.5) B32(-33,-3.5) B33(-34,-3.5) B34(-35,-3.5) B35(-36,-3.5) B36(-37,-3.5) B37(-38,-3.5) B38(-39,-3.5) B39(-40,-3.5) B40(-41,-3.5) B41(-42,-3.5) B42(-43,-3.5) B43(-44,-3.5) B44(-45,-3.5) B45(-46,-3.5) B46(-47,-3.5) B47(-48,-3.5) B49(-50,-3.5)
  rrect0% 0.7x3.2 smd far side paste-3.2: B17(-18,-4) B31(-32,-4) B48(-49,-4)
FGG400 [mm] "BGA, 400-Leads, Body 21x21mm, Pitch 1mm"
  round 0.5 smd: A1(-9.5,9.5) A2(-8.5,9.5) A3(-7.5,9.5) A4(-6.5,9.5) A5(-5.5,9.5) A6(-4.5,9.5) A7(-3.5,9.5) A8(-2.5,9.5) A9(-1.5,9.5) A10(-0.5,9.5) A11(0.5,9.5) A12(1.5,9.5) A13(2.5,9.5) A14(3.5,9.5) A15(4.5,9.5) A16(5.5,9.5) A17(6.5,9.5) A18(7.5,9.5) A19(8.5,9.5) A20(9.5,9.5) B1(-9.5,8.5) B2(-8.5,8.5) B3(-7.5,8.5) B4(-6.5,8.5) B5(-5.5,8.5) B6(-4.5,8.5) B7(-3.5,8.5) B8(-2.5,8.5) B9(-1.5,8.5) B10(-0.5,8.5) B11(0.5,8.5) B12(1.5,8.5) B13(2.5,8.5) B14(3.5,8.5) B15(4.5,8.5) B16(5.5,8.5) B17(6.5,8.5) B18(7.5,8.5) B19(8.5,8.5) B20(9.5,8.5) C1(-9.5,7.5) C2(-8.5,7.5) C3(-7.5,7.5) C4(-6.5,7.5) C5(-5.5,7.5) C6(-4.5,7.5) C7(-3.5,7.5) C8(-2.5,7.5) C9(-1.5,7.5) C10(-0.5,7.5) C11(0.5,7.5) C12(1.5,7.5) C13(2.5,7.5) C14(3.5,7.5) C15(4.5,7.5) C16(5.5,7.5) C17(6.5,7.5) C18(7.5,7.5) C19(8.5,7.5) C20(9.5,7.5) D1(-9.5,6.5) D2(-8.5,6.5) D3(-7.5,6.5) D4(-6.5,6.5) D5(-5.5,6.5) D6(-4.5,6.5) D7(-3.5,6.5) D8(-2.5,6.5) D9(-1.5,6.5) D10(-0.5,6.5) D11(0.5,6.5) D12(1.5,6.5) D13(2.5,6.5) D14(3.5,6.5) D15(4.5,6.5) D16(5.5,6.5) D17(6.5,6.5) D18(7.5,6.5) D19(8.5,6.5) D20(9.5,6.5) E1(-9.5,5.5) E2(-8.5,5.5) E3(-7.5,5.5) E4(-6.5,5.5) E5(-5.5,5.5) E6(-4.5,5.5) E7(-3.5,5.5) E8(-2.5,5.5) E9(-1.5,5.5) E10(-0.5,5.5) E11(0.5,5.5) E12(1.5,5.5) E13(2.5,5.5) E14(3.5,5.5) E15(4.5,5.5) E16(5.5,5.5) E17(6.5,5.5) E18(7.5,5.5) E19(8.5,5.5) E20(9.5,5.5) F1(-9.5,4.5) F2(-8.5,4.5) F3(-7.5,4.5) F4(-6.5,4.5) F5(-5.5,4.5) F6(-4.5,4.5) F7(-3.5,4.5) F8(-2.5,4.5) F9(-1.5,4.5) F10(-0.5,4.5) F11(0.5,4.5) F12(1.5,4.5) F13(2.5,4.5) F14(3.5,4.5) F15(4.5,4.5) F16(5.5,4.5) F17(6.5,4.5) F18(7.5,4.5) F19(8.5,4.5) F20(9.5,4.5) G1(-9.5,3.5) G2(-8.5,3.5) G3(-7.5,3.5) G4(-6.5,3.5) G5(-5.5,3.5) G6(-4.5,3.5) G7(-3.5,3.5) G8(-2.5,3.5) G9(-1.5,3.5) G10(-0.5,3.5) G11(0.5,3.5) G12(1.5,3.5) G13(2.5,3.5) G14(3.5,3.5) G15(4.5,3.5) G16(5.5,3.5) G17(6.5,3.5) G18(7.5,3.5) G19(8.5,3.5) G20(9.5,3.5) H1(-9.5,2.5) H2(-8.5,2.5) H3(-7.5,2.5) H4(-6.5,2.5) H5(-5.5,2.5) H6(-4.5,2.5) H7(-3.5,2.5) H8(-2.5,2.5) H9(-1.5,2.5) H10(-0.5,2.5) H11(0.5,2.5) H12(1.5,2.5) H13(2.5,2.5) H14(3.5,2.5) H15(4.5,2.5) H16(5.5,2.5) H17(6.5,2.5) H18(7.5,2.5) H19(8.5,2.5) H20(9.5,2.5) J1(-9.5,1.5) J2(-8.5,1.5) J3(-7.5,1.5) J4(-6.5,1.5) J5(-5.5,1.5) J6(-4.5,1.5) J7(-3.5,1.5) J8(-2.5,1.5) J9(-1.5,1.5) J10(-0.5,1.5) J11(0.5,1.5) J12(1.5,1.5) J13(2.5,1.5) J14(3.5,1.5) J15(4.5,1.5) J16(5.5,1.5) J17(6.5,1.5) J18(7.5,1.5) J19(8.5,1.5) J20(9.5,1.5) K1(-9.5,0.5) K2(-8.5,0.5) K3(-7.5,0.5) K4(-6.5,0.5) K5(-5.5,0.5) K6(-4.5,0.5) K7(-3.5,0.5) K8(-2.5,0.5) K9(-1.5,0.5) K10(-0.5,0.5) K11(0.5,0.5) K12(1.5,0.5) K13(2.5,0.5) K14(3.5,0.5) K15(4.5,0.5) K16(5.5,0.5) K17(6.5,0.5) K18(7.5,0.5) K19(8.5,0.5) K20(9.5,0.5) L1(-9.5,-0.5) L2(-8.5,-0.5) L3(-7.5,-0.5) L4(-6.5,-0.5) L5(-5.5,-0.5) L6(-4.5,-0.5) L7(-3.5,-0.5) L8(-2.5,-0.5) L9(-1.5,-0.5) L10(-0.5,-0.5) L11(0.5,-0.5) L12(1.5,-0.5) L13(2.5,-0.5) L14(3.5,-0.5) L15(4.5,-0.5) L16(5.5,-0.5) L17(6.5,-0.5) L18(7.5,-0.5) L19(8.5,-0.5) L20(9.5,-0.5) M1(-9.5,-1.5) M2(-8.5,-1.5) M3(-7.5,-1.5) M4(-6.5,-1.5) M5(-5.5,-1.5) M6(-4.5,-1.5) M7(-3.5,-1.5) M8(-2.5,-1.5) M9(-1.5,-1.5) M10(-0.5,-1.5) M11(0.5,-1.5) M12(1.5,-1.5) M13(2.5,-1.5) M14(3.5,-1.5) M15(4.5,-1.5) M16(5.5,-1.5) M17(6.5,-1.5) M18(7.5,-1.5) M19(8.5,-1.5) M20(9.5,-1.5) N1(-9.5,-2.5) N2(-8.5,-2.5) N3(-7.5,-2.5) N4(-6.5,-2.5) N5(-5.5,-2.5) N6(-4.5,-2.5) N7(-3.5,-2.5) N8(-2.5,-2.5) N9(-1.5,-2.5) N10(-0.5,-2.5) N11(0.5,-2.5) N12(1.5,-2.5) N13(2.5,-2.5) N14(3.5,-2.5) N15(4.5,-2.5) N16(5.5,-2.5) N17(6.5,-2.5) N18(7.5,-2.5) N19(8.5,-2.5) N20(9.5,-2.5) P1(-9.5,-3.5) P2(-8.5,-3.5) P3(-7.5,-3.5) P4(-6.5,-3.5) P5(-5.5,-3.5) P6(-4.5,-3.5) P7(-3.5,-3.5) P8(-2.5,-3.5) P9(-1.5,-3.5) P10(-0.5,-3.5) P11(0.5,-3.5) P12(1.5,-3.5) P13(2.5,-3.5) P14(3.5,-3.5) P15(4.5,-3.5) P16(5.5,-3.5) P17(6.5,-3.5) P18(7.5,-3.5) P19(8.5,-3.5) P20(9.5,-3.5) R1(-9.5,-4.5) R2(-8.5,-4.5) R3(-7.5,-4.5) R4(-6.5,-4.5) R5(-5.5,-4.5) R6(-4.5,-4.5) R7(-3.5,-4.5) R8(-2.5,-4.5) R9(-1.5,-4.5) R10(-0.5,-4.5) R11(0.5,-4.5) R12(1.5,-4.5) R13(2.5,-4.5) R14(3.5,-4.5) R15(4.5,-4.5) R16(5.5,-4.5) R17(6.5,-4.5) R18(7.5,-4.5) R19(8.5,-4.5) R20(9.5,-4.5) T1(-9.5,-5.5) T2(-8.5,-5.5) T3(-7.5,-5.5) T4(-6.5,-5.5) T5(-5.5,-5.5) T6(-4.5,-5.5) T7(-3.5,-5.5) T8(-2.5,-5.5) T9(-1.5,-5.5) T10(-0.5,-5.5) T11(0.5,-5.5) T12(1.5,-5.5) T13(2.5,-5.5) T14(3.5,-5.5) T15(4.5,-5.5) T16(5.5,-5.5) T17(6.5,-5.5) T18(7.5,-5.5) T19(8.5,-5.5) T20(9.5,-5.5) U1(-9.5,-6.5) U2(-8.5,-6.5) U3(-7.5,-6.5) U4(-6.5,-6.5) U5(-5.5,-6.5) U6(-4.5,-6.5) U7(-3.5,-6.5) U8(-2.5,-6.5) U9(-1.5,-6.5) U10(-0.5,-6.5) U11(0.5,-6.5) U12(1.5,-6.5) U13(2.5,-6.5) U14(3.5,-6.5) U15(4.5,-6.5) U16(5.5,-6.5) U17(6.5,-6.5) U18(7.5,-6.5) U19(8.5,-6.5) U20(9.5,-6.5) V1(-9.5,-7.5) V2(-8.5,-7.5) V3(-7.5,-7.5) V4(-6.5,-7.5) V5(-5.5,-7.5) V6(-4.5,-7.5) V7(-3.5,-7.5) V8(-2.5,-7.5) V9(-1.5,-7.5) V10(-0.5,-7.5) V11(0.5,-7.5) V12(1.5,-7.5) V13(2.5,-7.5) V14(3.5,-7.5) V15(4.5,-7.5) V16(5.5,-7.5) V17(6.5,-7.5) V18(7.5,-7.5) V19(8.5,-7.5) V20(9.5,-7.5) W1(-9.5,-8.5) W2(-8.5,-8.5) W3(-7.5,-8.5) W4(-6.5,-8.5) W5(-5.5,-8.5) W6(-4.5,-8.5) W7(-3.5,-8.5) W8(-2.5,-8.5) W9(-1.5,-8.5) W10(-0.5,-8.5) W11(0.5,-8.5) W12(1.5,-8.5) W13(2.5,-8.5) W14(3.5,-8.5) W15(4.5,-8.5) W16(5.5,-8.5) W17(6.5,-8.5) W18(7.5,-8.5) W19(8.5,-8.5) W20(9.5,-8.5) Y1(-9.5,-9.5) Y2(-8.5,-9.5) Y3(-7.5,-9.5) Y4(-6.5,-9.5) Y5(-5.5,-9.5) Y6(-4.5,-9.5) Y7(-3.5,-9.5) Y8(-2.5,-9.5) Y9(-1.5,-9.5) Y10(-0.5,-9.5) Y11(0.5,-9.5) Y12(1.5,-9.5) Y13(2.5,-9.5) Y14(3.5,-9.5) Y15(4.5,-9.5) Y16(5.5,-9.5) Y17(6.5,-9.5) Y18(7.5,-9.5) Y19(8.5,-9.5) Y20(9.5,-9.5)
  silkscreen extent -11.27,-10.5 10.5,10.5, body extent -10.5,-10.5 10.5,10.5, height 2.43
"FIDUCIAL ROUND" [mm] "FIDUCIAL ROUND"
  round 1.5 all layers, no hole paste-1.524 mask+1.1: 0(0,0)
  Top Layer circle w0.127: c0,0 r1.778
  Bottom Layer circle w0.127: c0,0 r1.778
FPC-XXS1VN3R [mm] "Connector; ZIF FPC 40 Position; 0.5mm Spaced Vertical Mounting"
  rrect50% 0.4x1.524 smd: 1(-9.75,-0.975) 2(-9.25,0.975) 3(-8.75,-0.975) 4(-8.25,0.975) 5(-7.75,-0.975) 6(-7.25,0.975) 7(-6.75,-0.975) 8(-6.25,0.975) 9(-5.75,-0.975) 10(-5.25,0.975) 11(-4.75,-0.975) 12(-4.25,0.975) 13(-3.75,-0.975) 14(-3.25,0.975) 15(-2.75,-0.975) 16(-2.25,0.975) 17(-1.75,-0.975) 18(-1.25,0.975) 19(-0.75,-0.975) 20(-0.25,0.975) 21(0.25,-0.975) 22(0.75,0.975) 23(1.25,-0.975) 24(1.75,0.975) 25(2.25,-0.975) 26(2.75,0.975) 27(3.25,-0.975) 28(3.75,0.975) 29(4.25,-0.975) 30(4.75,0.975) 31(5.25,-0.975) 32(5.75,0.975) 33(6.25,-0.975) 34(6.75,0.975) 35(7.25,-0.975) 36(7.75,0.975) 37(8.25,-0.975) 38(8.75,0.975) 39(9.25,-0.975) 40(9.75,0.975)
  rect 2x2.4 smd: 41(-11.55,0) 42(11.55,0)
  silkscreen extent -10.58,-2.12 -10.33,-1.88, body extent -12.12,-1.45 12.18,1.48, height 4.47
H11L1SR2VM [mil] "Recommended pad layout for surface mount leadform"
  rect 70x80 smd: 1(-100,-182.48) 2(0,-182.48) 3(100,-182.48) 4(100,182.48) 5(0,182.48) 6(-100,182.48)
  silkscreen extent -162,-187 130,137, body extent -174,-196 176,190, height 157
HDR1X2 [mm]
  rect 1.5x1.5 hole 0.9: 1(-0.01,0.007)
  round 1.5 hole 0.9: 2(2.53,0.007)
  silkscreen extent -1.28,-1.26 3.8,1.28, body extent -1.28,-1.26 3.8,1.28, height 8.41
HDR2X2 [mm]
  rect 1.5x1.5 hole 0.9: 1(0,0)
  round 1.5 hole 0.9: 2(0,2.54) 3(2.54,0) 4(2.54,2.54)
  silkscreen extent -1.27,-1.27 3.81,3.81, body extent -1.27,-1.27 3.81,3.81, height 8.41
HDR2X10 [mm]
  rect 1.5x1.5 hole 0.9: 1(0,0)
  round 1.5 hole 0.9: 2(0,2.54) 3(2.54,0) 4(2.54,2.54) 5(5.08,0) 6(5.08,2.54) 7(7.62,0) 8(7.62,2.54) 9(10.16,0) 10(10.16,2.54) 11(12.7,0) 12(12.7,2.54) 13(15.24,0) 14(15.24,2.54) 15(17.78,0) 16(17.78,2.54) 17(20.32,0) 18(20.32,2.54) 19(22.86,0) 20(22.86,2.54)
  silkscreen extent -1.27,-1.27 24.13,3.81, body extent -1.28,-1.26 24.12,3.82, height 8.38
IM03GR [mm]
  rrect50% 2x1 smd paste+0 mask+0: 1(0,0) 2(0,3.2) 3(0,5.4) 4(0,7.6) 5(-6,7.6) 6(-6,5.4) 7(-6,3.2) 8(-6,0)
  silkscreen extent -6.1,-1.5 0.1,8.8, body extent -6.79,-1.02 0.7,8.64, height 3.8
INDC3225 [mm]
  rect 1x2.5 smd: 1(-1.5,0) 2(1.5,0)
  silkscreen extent -0.6,-1.6 0.6,1.6, body extent -1.38,-1.14 1.41,1.15, height 1.78
KLD-0202 [mm]
  oval 2x4.5 hole 1 slot 3.5 at 90 deg: 1(13.7,0)
  oval 2x4 hole 1 slot 3 at 90 deg: 2(7.5,0)
  oval 4x2 hole 1 slot 3 at 0 deg: 3(10.5,-5)
  silkscreen extent 0,-4.5 13.7,4.5, body extent -0.15,-5 14.35,4.5, height 11
KME04-USBMU03A01-1 [mm] "KME04-USBMU03A01-1"
  rrect50% 2.8x0.5 smd: 1(0,0) 2(0,-0.8) 3(0,-1.6) 4(0,-2.4) 5(0,-3.2)
  rrect50% 3.5x2.05 smd: 6(0.025,3.325) 8(0.025,-6.525)
  rrect50% 4x2.05 smd: 7(-4.225,3.325) 9(-4.225,-6.525)
  round 0.9 hole 0.9 unplated: X(-2.325,-3.8) Y(-2.325,0.6)
  silkscreen extent -8.25,-4.85 2,1.65, body extent -8.22,-6.56 0.78,3.34, height 3.95
KMFCDIN76005 [mm]
  round 2.5 hole 1.3: 1(7.5,3.75) 2(0,3.75) 3(-7.5,3.75) 4(5,6.25) 5(-5,6.25) MH1(2.5,-6.25) MH2(-2.5,-6.25)
  silkscreen extent -10.5,-8.75 10.5,7.25, body extent -10.34,-8.95 10.36,7.31, height 21.4
KMRJ103-5-508-6 [mm] "5.0mm pitch terminal block, 6-way"
  round 2.1 hole 1.2: 1(-12.5,0) 2(-7.5,0) 3(-2.5,0) 4(2.5,0) 5(7.5,0) 6(12.5,0)
  silkscreen extent -15.05,-7.8 15.05,5.5, body extent -15.83,-6.4 14.91,7, height 15.3
KMRJ103-5-508-12 [mm] "5.0mm pitch terminal block, 12-way"
  round 2.1 hole 1.2: 1(-27.5,0) 2(-22.5,0) 3(-17.5,0) 4(-12.5,0) 5(-7.5,0) 6(-2.5,0) 7(2.5,0) 8(7.5,0) 9(12.5,0) 10(17.5,0) 11(22.5,0) 12(27.5,0)
  silkscreen extent -30.05,-7.8 30.05,5.5, body extent -30.7,-6.4 30.04,7, height 15.3
KSDC012551#1 [mm] "SD Card socket"
  rrect50% 1.16x2.5 smd: 1(-6.48,-12.15) 2(-3.98,-12.15) 3(-0.68,-12.15) 4(1.03,-12.15) 5(3.53,-12.15) 6(6.03,-12.15) 7(8.45,-12.15) 8(10.15,-12.15) 9(-8.98,-12.15) CD(-2.33,-12.15) WP(13.5,-12.15)
  rect 2.2x2.2 smd: GND1(14,10.05)
  rect 2.2x2.134 smd: GND2(-14,10.05)
  round 1.55 hole 1.55 unplated: MH1(12.5,12.15) MH2(-11.7,12.15)
  silkscreen extent -14.22,-11.4 14.22,17.4, body extent -14.32,-12.74 14.4,21.53, height 2.9
KSDC012551#2 [mm] "SD Card socket"
  rrect50% 1.16x2.5 smd: 1(-6.48,-12.15) 2(-3.98,-12.15) 3(-0.68,-12.15) 4(1.03,-12.15) 5(3.53,-12.15) 6(6.03,-12.15) 7(8.45,-12.15) 8(10.15,-12.15) 9(-8.98,-12.15) CD(-2.33,-12.15) WP(13.5,-12.15)
  rrect50% 1.524x3.048 smd: GND1(14,10.05) GND2(-14,10.05)
  round 1.55 hole 1.55 unplated: MH1(12.5,12.15) MH2(-11.7,12.15)
  silkscreen extent -14.22,-11.4 14.22,17.4, body extent -14.32,-12.74 14.4,21.53, height 2.9
LEAD_FREE_S [mil]
  silkscreen extent -125,-125 125,125
LOGO-ALTIUM-NEW [mil]
  silkscreen extent -211,-34 202,54
MF_SM250 [mm] "PTC Resetatable Fuse"
  rect 2.3x4.6 smd: 1(-2.323,0.127) 2(6.077,0.127)
  silkscreen extent -4.12,-2.62 7.88,2.88, body extent -2.78,-3.01 6.33,3.34, height 3.17
MINIDIN6PURPLE [mm]
  round 1.6 hole 0.9: 1(8.45,-1.25) 2(8.45,1.25) 3(8.45,-3.25) 4(8.45,3.25) 5(10.95,-3.25) 6(10.95,3.25)
  round 3.5 hole 2.3: MH1(4.7,0)
  oval 4.4x2.4 hole 0.9 slot 2.4 at 0 deg: MH2(5.45,6.905) MH3(5.45,-6.595)
  silkscreen extent -0.05,-7 12.7,7, body extent -0.1,-7.03 12.7,6.97, height 13
"NANOBOARD LOGO" [mil]
  silkscreen extent -442,-67 456,59
"NB2STR01 Blank PCB" [mil]
NETTIE-SMT2-8X8#1 [mil]
  rect 21x12 smd paste-22 mask-22: 1(-47.2,-0.24) 2(-27.2,-0.24)
NETTIE-SMT2-8X8#2 [mil]
  rect 21x12 smd paste-22 mask-22: 1(-45,0) 2(-25,0)
NETTIE-SMT2-8X8#3 [mil]
  rect 21x12 smd paste-22 mask-22: 1(-47.2,0) 2(-27.2,0)
NETTIE-SMT2-8X8#4 [mil]
  rect 21x12 smd paste-22 mask-22: 1(-45,-1.11) 2(-25,-1.11)
NETTIE-SMT2-8X8#5 [mil]
  rect 21x12 smd paste-22 mask-22: 1(-30.08,-2.56) 2(-10.08,-2.56)
NETTIE-SMT2-8X8#6 [mil]
  rect 21x12 smd paste-22 mask-22: 1(-30.08,3.07) 2(-10.08,3.07)
NETTIE-SMT2-8X8#7 [mil]
  rect 21x12 smd paste-22 mask-22: 1(-30.08,-4.49) 2(-10.08,-4.49)
NETTIE-SMT2-8X8#8 [mil]
  rect 21x12 smd paste-22 mask-22: 1(-31.22,-2.28) 2(-51.22,-2.28)
NETTIE-SMT2-8X8#9 [mil]
  rect 21x12 smd paste-22 mask-22: 1(-31.06,3.03) 2(-11.06,3.03)
NETTIE-SMT2-8X8#10 [mil]
  rect 21x12 smd paste-22 mask-22: 1(-30.08,-1.3) 2(-10.08,-1.3)
NETTIE-SMT2-8X8#11 [mil]
  rect 21x12 smd paste-22 mask-22: 1(-31.06,3.66) 2(-11.06,3.66)
NETTIE-SMT2-8X8#12 [mil]
  rect 21x12 smd paste-22 mask-22: 1(-30,-0.46) 2(-10,-0.46)
NETTIE-SMT2-8X8#13 [mil]
  rect 21x12 smd paste-22 mask-22: 1(-30,-2.14) 2(-10,-2.14)
NETTIE-SMT2-8X8#14 [mil]
  rect 21x12 smd paste-22 mask-22: 1(-30,-1.51) 2(-10,-1.51)
NETTIE-SMT2-8X8#15 [mil]
  rect 21x12 smd paste-22 mask-22: 1(-30,-1.76) 2(-10,-1.76)
NETTIE-SMT2-8X8#16 [mil]
  rect 20x12 smd paste-20 mask-4.33: 1(-30,1.39) 2(-10,1.39)
NETTIE-SMT2-8X8#17 [mil]
  rect 21x12 smd paste-22 mask-22: 1(-30,0.93) 2(-10,0.93)
NETTIE-SMT2-8X8#18 [mil]
  rect 21x12 smd paste-22 mask-22: 1(-30,-0.88) 2(-10,-0.88)
NETTIE-SMT2-8X8#19 [mil]
  rect 21x12 smd paste-22 mask-22: 1(-30,-2.39) 2(-10,-2.39)
NETTIE-SMT2-8X8#20 [mil]
  rect 21x12 smd paste-22 mask-22: 1(-40,0) 2(-20,0)
NETTIE-SMT2-8X8#21 [mil]
  rect 21x12 smd paste-22 mask-22: 1(-30,0) 2(-10,0)
NETTIE-SMT2-31X39 [mil]
  rect 40x31.5 smd paste-19.68 mask-19.68: 1(-66.57,0.24) 2(-27.2,0.24)
NETTIE-SMT2-31X51 [mil]
  rect 52x31.5 smd paste-52 mask-19.68: 1(-35.08,0.24) 2(16.1,0.24)
PERIPHERAL_BOARD_1SLOT [mil] "Outline of 2-Slot Peripheral Board"
  Top Layer region: 728.35,3228.35 653.54,3153.54 287.4,3153.54 212.6,3228.35
  Top Layer region: 0,2216.54 74.8,2291.34 74.8,2940.94 0,3015.75
  Top Layer region: 0,452.76 74.8,527.56 74.8,937.01 0,1011.81
  Top Layer region: 2440.94,2216.54 2366.14,2291.34 2366.14,2940.94 2440.94,3015.75
  Top Layer region: 2440.94,452.76 2366.14,527.56 2366.14,937.01 2440.94,1011.81
  silkscreen extent 0,0 2441,3228
PH-2 [mm]
  rect 1.5x1.5 hole 0.75: 1(0,0)
  round 1.5 hole 0.75: 2(2,0)
  silkscreen extent -2.15,-2.85 4.15,1.85, body extent -3.88,-5.28 5.91,4.33, height 6
POT-R0911G-A1 [mm]
  round 2 hole 0.9: 1(-2.5,0) 2(0,0) 3(2.5,0) 4(-2.5,-2.5) 5(0,-2.5) 6(2.5,-2.5)
  silkscreen extent -4.9,-22.3 4.5,2.3, body extent -5.73,-27.97 5.76,1.5, height 12.64
PT4812 [mm] "Transformer for Digital Audio Data Transmission"
  rrect50% 1.27x3.05 smd: 1(0,0) 2(2.54,0) 3(5.08,0) 4(7.62,0) 5(7.62,13.21) 6(5.08,13.21) 7(2.54,13.21) 8(0,13.21)
  silkscreen extent -2.22,1.52 9.84,11.69, body extent -2.28,-0.29 9.78,13.24, height 8.86
QFN50P800X800_HS-57 [mm] "Quad Flat No Lead; 56 Terminals; Body 8 x 8 mm; Pitch 0.5 mm, Punch Version"
  rrect50% 0.305x0.86 smd mask+0.051: 1(-3.25,-3.92) 14(3.25,-3.92) 29(3.25,3.92) 42(-3.25,3.92)
  rrect50% 0.305x0.86 smd mask+0.038: 2(-2.75,-3.92) 3(-2.25,-3.92) 4(-1.75,-3.92) 5(-1.25,-3.92) 6(-0.75,-3.92) 7(-0.25,-3.92) 8(0.25,-3.92) 9(0.75,-3.92) 10(1.25,-3.92) 11(1.75,-3.92) 12(2.25,-3.92) 13(2.75,-3.92) 30(2.75,3.92) 31(2.25,3.92) 32(1.75,3.92) 33(1.25,3.92) 34(0.75,3.92) 35(0.25,3.92) 36(-0.25,3.92) 37(-0.75,3.92) 38(-1.25,3.92) 39(-1.75,3.92) 40(-2.25,3.92) 41(-2.75,3.92)
  rrect50% 0.86x0.305 smd mask+0.051: 15(3.92,-3.25) 28(3.92,3.25) 43(-3.92,3.25) 56(-3.92,-3.25)
  rrect50% 0.86x0.305 smd mask+0.038: 16(3.92,-2.75) 17(3.92,-2.25) 18(3.92,-1.75) 19(3.92,-1.25) 20(3.92,-0.75) 21(3.92,-0.25) 22(3.92,0.25) 23(3.92,0.75) 24(3.92,1.25) 25(3.92,1.75) 26(3.92,2.25) 27(3.92,2.75) 44(-3.92,2.75) 45(-3.92,2.25) 46(-3.92,1.75) 47(-3.92,1.25) 48(-3.92,0.75) 49(-3.92,0.25) 50(-3.92,-0.25) 51(-3.92,-0.75) 52(-3.92,-1.25) 53(-3.92,-1.75) 54(-3.92,-2.25) 55(-3.92,-2.75)
  Top Layer region: -2.75,2.75 2.75,2.75 2.75,-2.75 -2.75,-2.75
  silkscreen extent -4.05,-4.83 4.05,4.05, body extent -4.32,-4.24 4.26,4.28, height 0.55
RESC1005-STAR [mm] "Chip Inductor 1005"
  rect 0.575x0.6 smd: 1(-0.538,0) 2(0.538,0)
  silkscreen extent -0.05,-0.38 0.05,0.38, body extent -0.71,-0.25 0.72,0.26, height 0.25
RESC2012-STAR [mm] "0805 Resistor SMD - Startronics"
  rect 1x1.25 smd: 1(-1,0) 2(1,0)
  silkscreen extent -0.4,-1 0.4,1, body extent -1.03,-0.54 1.07,0.57, height 0.25
RESC3216 [mm]
  rect 1.6x1.8 smd: 1(-1.4,0) 2(1.4,0)
  silkscreen extent -0.3,-0.8 0.3,0.8, body extent -1.33,-0.81 1.37,0.85, height 0.55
